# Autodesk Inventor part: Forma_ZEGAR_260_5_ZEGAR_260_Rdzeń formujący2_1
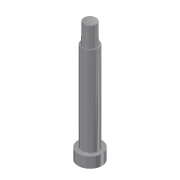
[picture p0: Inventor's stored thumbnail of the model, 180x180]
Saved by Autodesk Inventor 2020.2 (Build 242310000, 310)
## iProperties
Created: 2015-01
Part Number: Forma_ZEGAR_260_5_ZEGAR_260_Rdzeń formujący2_1
Material: Ogólny
Description: Straight Core Pin
Document SubType Name: Modeling
Designer: F.Stasiak
Density: 1 g/cm^3
Appearance: Domyślna
Catalog Web Link: www.expertbooks.pl
Manager: www.cadconsulting.pl
Company: Fabian Stasiak CAD Consulting
Author: F.Stasiak
Subject: Zbiór ćwiczeń. Autodesk Inventor 2020. Kurs Professional
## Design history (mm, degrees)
node "Forma_ZEGAR_260_4_ZEGAR_260_Rdzeń formujący2_Base"
feature "Solid1::Forma_ZEGAR_260_4_ZEGAR_260_Rdzeń formujący2_Base"
tag "Bryła wyprowadzona1"
node "Bryła1"
feature "Forma_ZEGAR_260_4_ZEGAR_260_Rdzeń formujący2_Base_Bodies"
